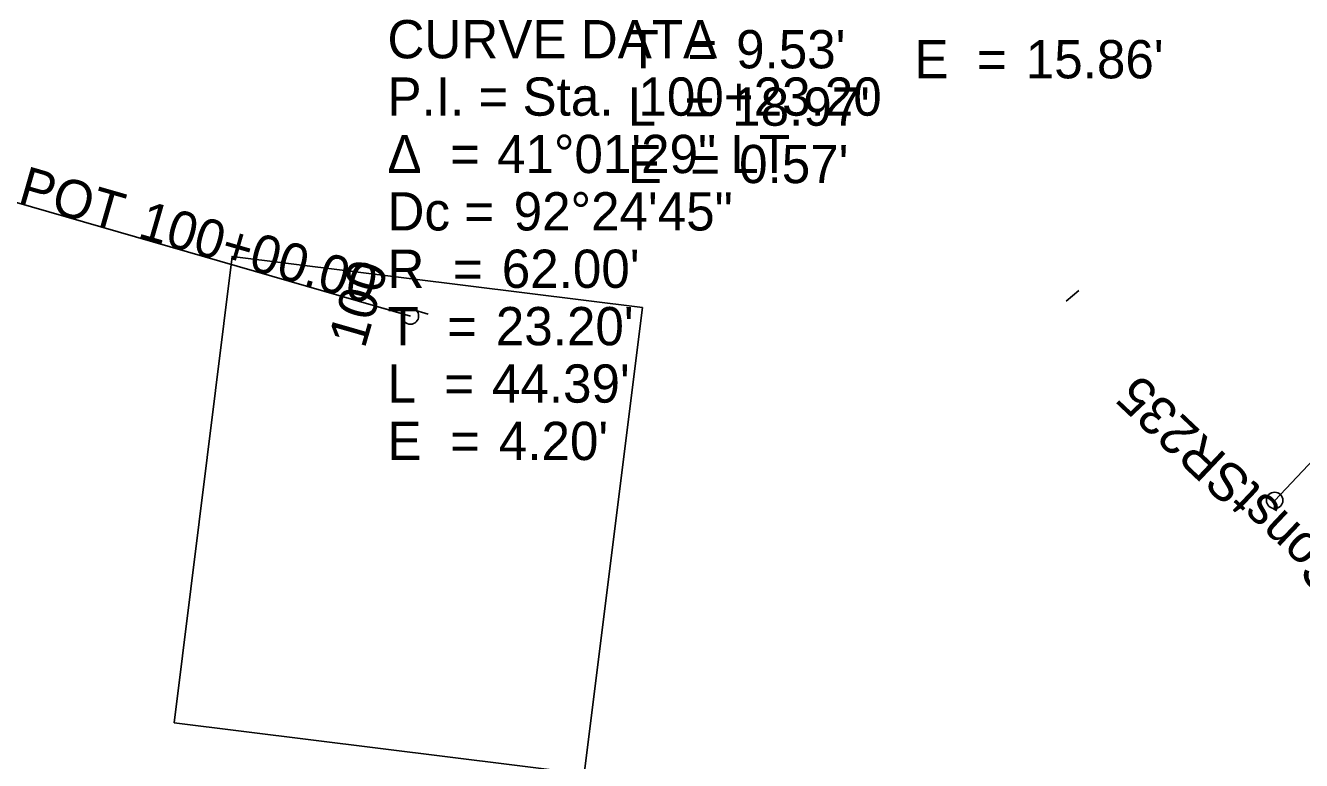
# Model space of a CAD drawing. Extents: x 1564517 to 1565226, y 635740 to 637455.
# Drawn here: x 1564729.9 to 1564823.3, y 636474.7 to 636528.5 of the extents above; entities that cross this region are included whole.
import ezdxf

# ---------------------------------------------------------------- set-up
doc = ezdxf.new("R2010")
doc.units = 0
for name, color, linetype in [('GE_P_Alignment_1000_Cardinal_Points', 7, 'Continuous'), ('GE_P_Alignment_1000_Distances', 7, 'Continuous'), ('GE_P_Alignment_500_Cardinal_Points', 7, 'Continuous'), ('GE_P_Alignment_500_Distances', 7, 'Continuous'), ('GK_Drainage_Nodes', 7, 'Continuous'), ('SC_Scratch10', 7, 'Continuous'), ('UT_P_Water', 7, 'Continuous'), ('UT_P_Water_Cells', 7, 'Continuous'), ('UT_X_Electric', 7, 'Continuous'), ('UT_X_Sanitary_Pressure_Line', 7, 'Continuous'), ('UT_X_Water_Cells', 7, 'Continuous')]:
    doc.layers.add(name, color=color, linetype=linetype)

msp = doc.modelspace()

# ---------------------------------------------------------------- linework, layer by layer
at = {"layer": 'GE_P_Alignment_1000_Cardinal_Points'}
msp.add_line((1564821.361, 636493.748), (1564852.269, 636526.454), dxfattribs=at)
msp.add_circle((1564821.361, 636493.748), 0.6, dxfattribs=at)
at = {"layer": 'GE_P_Alignment_500_Cardinal_Points'}
msp.add_line((1564821.361, 636493.748), (1564852.269, 636526.454), dxfattribs=at)
msp.add_circle((1564821.361, 636493.748), 0.6, dxfattribs=at)
at = {"layer": 'UT_P_Water_Cells'}
for q in [(1564714.868, 636519.694), (1564756.189, 636507.794)]:
    msp.add_line((1564758.111, 636507.24), q, dxfattribs=at)
msp.add_circle((1564758.111, 636507.24), 0.6, dxfattribs=at)
at = {"layer": 'UT_X_Electric'}
msp.add_lwpolyline([(1564740.807, 636477.476), (1564745.056, 636511.601), (1564775.082, 636507.863), (1564770.834, 636473.738)], close=True, dxfattribs=at)
at = {"layer": 'UT_X_Sanitary_Pressure_Line'}
for q in [(1564714.868, 636519.694), (1564756.189, 636507.794)]:
    msp.add_line((1564758.111, 636507.24), q, dxfattribs=at)
msp.add_circle((1564758.111, 636507.24), 0.6, dxfattribs=at)
at = {"layer": 'UT_X_Water_Cells'}
for p, q in [((1564807.022, 636509.1), (1564806.096, 636508.337)), ((1564758.111, 636507.24), (1564756.189, 636507.794)), ((1564758.25, 636507.716), (1564759.401, 636507.377))]:
    msp.add_line(p, q, dxfattribs=at)

# ---------------------------------------------------------------- texts
at = {"layer": 'GE_P_Alignment_1000_Distances'}
msp.add_text('CL_ConstSR235', height=2.8, rotation=136.61917, dxfattribs=at).set_placement((1564831.892, 636483.795))
at = {"layer": 'GE_P_Alignment_500_Distances'}
msp.add_text('CL_ConstSR235', height=2.8, rotation=136.61917, dxfattribs=at).set_placement((1564831.892, 636483.795))
at = {"layer": 'GK_Drainage_Nodes'}
for s, p in [('CURVE DATA', (1564756.427, 636526.1)), ('T  = ', (1564774.011, 636525.365)), ("9.53'", (1564781.944, 636525.365)), ('E  = ', (1564794.993, 636524.633)), ("15.86'", (1564803.146, 636524.633)), ('P.I. = Sta. ', (1564756.427, 636521.9)), ('100+23.20', (1564774.795, 636521.9)), ('L  = ', (1564774.011, 636521.165)), ("18.97'", (1564781.658, 636521.165)), ('Δ  = ', (1564756.427, 636517.7)), ('41°01\'29" LT', (1564764.449, 636517.7)), ('E  = ', (1564774.011, 636516.965)), ("0.57'", (1564782.164, 636516.965)), ('Dc = ', (1564756.427, 636513.5)), ('92°24\'45"', (1564765.665, 636513.5)), ('R  = ', (1564756.427, 636509.3)), ("62.00'", (1564764.795, 636509.3)), ('T  = ', (1564756.427, 636505.1)), ("23.20'", (1564764.359, 636505.1)), ('L  = ', (1564756.427, 636500.9)), ("44.39'", (1564764.073, 636500.9)), ('E  = ', (1564756.427, 636496.7)), ("4.20'", (1564764.579, 636496.7))]:
    msp.add_text(s, height=2.8, dxfattribs=at).set_placement(p)
at = {"layer": 'SC_Scratch10'}
for s, p in [('CURVE DATA', (1564756.427, 636526.1)), ('T  = ', (1564774.011, 636525.365)), ("9.53'", (1564781.944, 636525.365)), ('E  = ', (1564794.993, 636524.633)), ("15.86'", (1564803.146, 636524.633)), ('P.I. = Sta. ', (1564756.427, 636521.9)), ('100+23.20', (1564774.795, 636521.9)), ('L  = ', (1564774.011, 636521.165)), ("18.97'", (1564781.658, 636521.165)), ('Δ  = ', (1564756.427, 636517.7)), ('41°01\'29" LT', (1564764.449, 636517.7)), ('E  = ', (1564774.011, 636516.965)), ("0.57'", (1564782.164, 636516.965)), ('Dc = ', (1564756.427, 636513.5)), ('92°24\'45"', (1564765.665, 636513.5)), ('R  = ', (1564756.427, 636509.3)), ("62.00'", (1564764.795, 636509.3)), ('T  = ', (1564756.427, 636505.1)), ("23.20'", (1564764.359, 636505.1)), ('L  = ', (1564756.427, 636500.9)), ("44.39'", (1564764.073, 636500.9)), ('E  = ', (1564756.427, 636496.7)), ("4.20'", (1564764.579, 636496.7))]:
    msp.add_text(s, height=2.8, dxfattribs=at).set_placement(p)
at = {"layer": 'UT_P_Water'}
for s, p in [('CURVE DATA', (1564756.427, 636526.1)), ('T  = ', (1564774.011, 636525.365)), ("9.53'", (1564781.944, 636525.365)), ('E  = ', (1564794.993, 636524.633)), ("15.86'", (1564803.146, 636524.633)), ('P.I. = Sta. ', (1564756.427, 636521.9)), ('100+23.20', (1564774.795, 636521.9)), ('L  = ', (1564774.011, 636521.165)), ("18.97'", (1564781.658, 636521.165)), ('Δ  = ', (1564756.427, 636517.7)), ('41°01\'29" LT', (1564764.449, 636517.7)), ('E  = ', (1564774.011, 636516.965)), ("0.57'", (1564782.164, 636516.965)), ('Dc = ', (1564756.427, 636513.5)), ('92°24\'45"', (1564765.665, 636513.5)), ('R  = ', (1564756.427, 636509.3)), ("62.00'", (1564764.795, 636509.3)), ('T  = ', (1564756.427, 636505.1)), ("23.20'", (1564764.359, 636505.1)), ('L  = ', (1564756.427, 636500.9)), ("44.39'", (1564764.073, 636500.9)), ('E  = ', (1564756.427, 636496.7)), ("4.20'", (1564764.579, 636496.7))]:
    msp.add_text(s, height=2.8, dxfattribs=at).set_placement(p)
at = {"layer": 'UT_P_Water_Cells'}
for s, rotation, p in [('POT', 343.93404, (1564729.283, 636515.543)), ('100+00.00', 343.93404, (1564738.056, 636513.016)), ('100', 73.93404, (1564754.756, 636504.793))]:
    msp.add_text(s, height=2.8, rotation=rotation, dxfattribs=at).set_placement(p)
at = {"layer": 'UT_X_Sanitary_Pressure_Line'}
for s, rotation, p in [('POT', 343.93404, (1564729.283, 636515.543)), ('100+00.00', 343.93404, (1564738.056, 636513.016)), ('100', 73.93404, (1564754.756, 636504.793))]:
    msp.add_text(s, height=2.8, rotation=rotation, dxfattribs=at).set_placement(p)
at = {"layer": 'UT_X_Water_Cells'}
msp.add_text('100', height=2.8, rotation=73.93404, dxfattribs=at).set_placement((1564754.756, 636504.793))

doc.saveas('drawing.dxf')
